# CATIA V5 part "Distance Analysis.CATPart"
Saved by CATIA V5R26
Part number: Distance Analysis
Bounding box of the stored display mesh (mm): x 776.925 to 1383.486, y -778.325 to -680.757, z 495.275 to 525.127
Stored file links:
  D:\LinkedIn Learning\NURBS\CATIA\Class Parts\Distance Analysis.CATPart
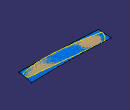
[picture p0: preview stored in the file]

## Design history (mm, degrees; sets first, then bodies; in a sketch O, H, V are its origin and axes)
AxisSystem1: origin (0, 0, 0), X (1, 0, 0), Y (0, 1, 0), Z (0, 0, 1)
Set1
  CLDGeom1 "Mesh"
  DatumSurface1
Body1 (main body)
